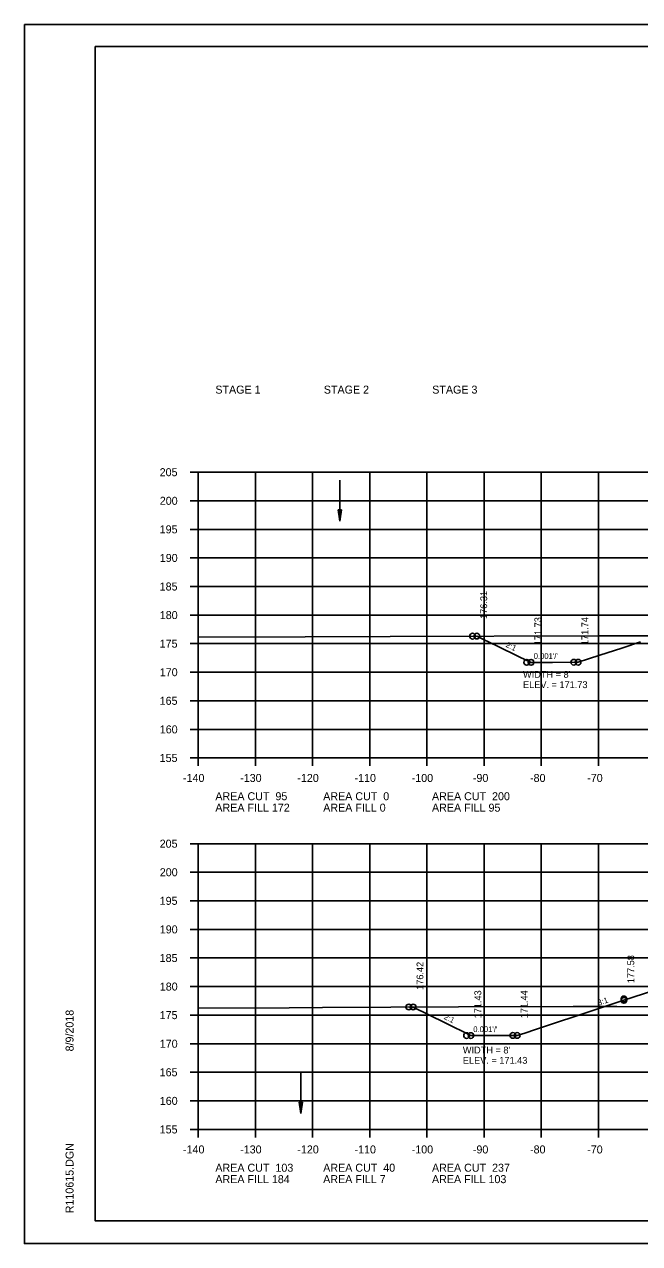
# Model space of a CAD drawing. Extents: x 1372132 to 1372465, y 380083 to 381790.
# Drawn here: x 1372131.6 to 1372239.2, y 381150.2 to 381363.5 of the extents above; entities that cross this region are included whole.
import ezdxf

# ---------------------------------------------------------------- set-up
doc = ezdxf.new("R2010")
doc.units = 0
for name, color, linetype in [('R_Axis', 7, 'Continuous'), ('R_Axis Annot', 7, 'Continuous'), ('R_Border', 7, 'Continuous'), ('R_Dimension', 7, 'Continuous'), ('R_Draft', 7, 'Continuous'), ('R_Exist Surface', 7, 'Continuous'), ('R_Fin Surface', 7, 'Continuous'), ('R_Grid', 7, 'Continuous'), ('R_No Plot', 7, 'Continuous'), ('R_Xsect Elev', 7, 'Continuous'), ('R_Xsect Slope', 7, 'Continuous')]:
    doc.layers.add(name, color=color, linetype=linetype)

msp = doc.modelspace()

# ---------------------------------------------------------------- linework, layer by layer
at = {"layer": 'R_Axis'}
for p, q in [((1372160.61, 381285.16), (1372162.01, 381285.16)), ((1372162.01, 381235.16), (1372162.01, 381285.16)), ((1372160.61, 381280.16), (1372162.01, 381280.16)), ((1372160.61, 381275.16), (1372162.01, 381275.16)), ((1372160.61, 381270.16), (1372162.01, 381270.16)), ((1372160.61, 381265.16), (1372162.01, 381265.16)), ((1372160.61, 381260.16), (1372162.01, 381260.16)), ((1372160.61, 381255.16), (1372162.01, 381255.16)), ((1372160.61, 381250.16), (1372162.01, 381250.16)), ((1372160.61, 381245.16), (1372162.01, 381245.16)), ((1372160.61, 381240.16), (1372162.01, 381240.16)), ((1372160.61, 381235.16), (1372162.01, 381235.16)), ((1372162.01, 381235.16), (1372442.01, 381235.16)), ((1372162.01, 381233.76), (1372162.01, 381235.16)), ((1372172.01, 381233.76), (1372172.01, 381235.16)), ((1372182.01, 381233.76), (1372182.01, 381235.16)), ((1372192.01, 381233.76), (1372192.01, 381235.16)), ((1372202.01, 381233.76), (1372202.01, 381235.16)), ((1372212.01, 381233.76), (1372212.01, 381235.16)), ((1372222.01, 381233.76), (1372222.01, 381235.16)), ((1372232.01, 381233.76), (1372232.01, 381235.16)), ((1372160.61, 381220.16), (1372162.01, 381220.16)), ((1372162.01, 381170.16), (1372162.01, 381220.16)), ((1372160.61, 381215.16), (1372162.01, 381215.16)), ((1372160.61, 381210.16), (1372162.01, 381210.16)), ((1372160.61, 381205.16), (1372162.01, 381205.16)), ((1372160.61, 381200.16), (1372162.01, 381200.16)), ((1372160.61, 381195.16), (1372162.01, 381195.16)), ((1372160.61, 381190.16), (1372162.01, 381190.16)), ((1372160.61, 381185.16), (1372162.01, 381185.16)), ((1372160.61, 381180.16), (1372162.01, 381180.16)), ((1372160.61, 381175.16), (1372162.01, 381175.16)), ((1372160.61, 381170.16), (1372162.01, 381170.16)), ((1372162.01, 381170.16), (1372442.01, 381170.16)), ((1372162.01, 381168.76), (1372162.01, 381170.16)), ((1372172.01, 381168.76), (1372172.01, 381170.16)), ((1372182.01, 381168.76), (1372182.01, 381170.16)), ((1372192.01, 381168.76), (1372192.01, 381170.16)), ((1372202.01, 381168.76), (1372202.01, 381170.16)), ((1372212.01, 381168.76), (1372212.01, 381170.16)), ((1372222.01, 381168.76), (1372222.01, 381170.16)), ((1372232.01, 381168.76), (1372232.01, 381170.16))]:
    msp.add_line(p, q, dxfattribs=at)
at = {"layer": 'R_Border'}
for p, q in [((1372144.01, 381359.62), (1372460.19, 381359.62)), ((1372144.01, 381154.16), (1372144.01, 381359.62)), ((1372144.01, 381154.16), (1372144.01, 381154.16)), ((1372460.19, 381154.16), (1372144.01, 381154.16))]:
    msp.add_line(p, q, dxfattribs=at)
at = {"layer": 'R_Dimension'}
for p, q in [((1372186.49, 381278.6), (1372186.79, 381276.6)), ((1372187.09, 381278.6), (1372186.49, 381278.6)), ((1372186.49, 381278.6), (1372186.79, 381276.6)), ((1372187.09, 381278.6), (1372186.49, 381278.6)), ((1372186.54, 381278.6), (1372186.79, 381276.93)), ((1372186.54, 381278.6), (1372186.79, 381276.93)), ((1372186.59, 381278.6), (1372186.79, 381277.28)), ((1372186.59, 381278.6), (1372186.79, 381277.28)), ((1372186.64, 381278.6), (1372186.79, 381277.61)), ((1372186.64, 381278.6), (1372186.79, 381277.61)), ((1372186.69, 381278.6), (1372186.79, 381277.95)), ((1372186.69, 381278.6), (1372186.79, 381277.95)), ((1372186.74, 381278.6), (1372186.79, 381278.28)), ((1372186.74, 381278.6), (1372186.79, 381278.28)), ((1372187.09, 381278.6), (1372186.79, 381276.6)), ((1372186.88, 381278.6), (1372186.79, 381277.95)), ((1372186.99, 381278.6), (1372186.79, 381277.28)), ((1372187.04, 381278.6), (1372186.79, 381276.93)), ((1372186.94, 381278.6), (1372186.79, 381277.61)), ((1372186.83, 381278.6), (1372186.79, 381278.28)), ((1372187.09, 381278.6), (1372186.79, 381276.6)), ((1372186.88, 381278.6), (1372186.79, 381277.95)), ((1372186.99, 381278.6), (1372186.79, 381277.28)), ((1372187.04, 381278.6), (1372186.79, 381276.93)), ((1372186.94, 381278.6), (1372186.79, 381277.61)), ((1372186.83, 381278.6), (1372186.79, 381278.28)), ((1372179.67, 381174.92), (1372179.97, 381172.92)), ((1372180.27, 381174.92), (1372179.67, 381174.92)), ((1372179.67, 381174.92), (1372179.97, 381172.92)), ((1372180.27, 381174.92), (1372179.67, 381174.92)), ((1372179.72, 381174.92), (1372179.97, 381173.26)), ((1372179.72, 381174.92), (1372179.97, 381173.26)), ((1372179.78, 381174.92), (1372179.97, 381173.6)), ((1372179.78, 381174.92), (1372179.97, 381173.6)), ((1372179.83, 381174.92), (1372179.97, 381173.93)), ((1372179.83, 381174.92), (1372179.97, 381173.93)), ((1372179.88, 381174.92), (1372179.97, 381174.27)), ((1372179.88, 381174.92), (1372179.97, 381174.27)), ((1372179.93, 381174.92), (1372179.97, 381174.61)), ((1372179.93, 381174.92), (1372179.97, 381174.61)), ((1372180.27, 381174.92), (1372179.97, 381172.92)), ((1372180.07, 381174.92), (1372179.97, 381174.27)), ((1372180.17, 381174.92), (1372179.97, 381173.6)), ((1372180.22, 381174.92), (1372179.97, 381173.26)), ((1372180.12, 381174.92), (1372179.97, 381173.93)), ((1372180.02, 381174.92), (1372179.97, 381174.61)), ((1372180.27, 381174.92), (1372179.97, 381172.92)), ((1372180.07, 381174.92), (1372179.97, 381174.27)), ((1372180.17, 381174.92), (1372179.97, 381173.6)), ((1372180.22, 381174.92), (1372179.97, 381173.26)), ((1372180.12, 381174.92), (1372179.97, 381173.93)), ((1372180.02, 381174.92), (1372179.97, 381174.61))]:
    msp.add_line(p, q, dxfattribs=at)
at = {"layer": 'R_Draft'}
for p, q in [((1372186.79, 381283.74), (1372186.79, 381276.6)), ((1372179.97, 381180.06), (1372179.97, 381172.92))]:
    msp.add_line(p, q, dxfattribs=at)
at = {"layer": 'R_Exist Surface'}
for points in [[(1372162.01, 381256.31), (1372180.72, 381256.37), (1372195.57, 381256.42), (1372231.92, 381256.55), (1372236.05, 381256.54), (1372246.27, 381256.51)], [(1372162.01, 381191.38), (1372177.94, 381191.45), (1372183.73, 381191.49), (1372195.68, 381191.57), (1372207.54, 381191.6), (1372227.58, 381191.66), (1372233.91, 381191.66), (1372235.26, 381191.67), (1372245.67, 381191.63)]]:
    msp.add_lwpolyline(points, dxfattribs=at)
at = {"layer": 'R_Fin Surface'}
for points in [[(1372210.75, 381256.48), (1372211.92, 381255.91), (1372214.24, 381254.78), (1372218.17, 381252.88), (1372220.22, 381251.89), (1372223.99, 381251.89), (1372228.45, 381251.9), (1372230.29, 381252.49), (1372232.23, 381253.12), (1372236.11, 381254.39), (1372239.36, 381255.46)], [(1372199.6, 381191.58), (1372205.21, 381188.81), (1372209.72, 381186.59), (1372212.24, 381186.6), (1372217.82, 381186.6), (1372219.13, 381187.03), (1372221.02, 381187.66), (1372231.75, 381191.19), (1372236.48, 381192.75), (1372241.71, 381194.47), (1372246.57, 381196.07), (1372247.93, 381196.05), (1372248.58, 381196.04), (1372251.05, 381196), (1372258.67, 381195.91), (1372258.96, 381195.91), (1372259.99, 381195.89), (1372268.77, 381195.71), (1372270.22, 381195.68), (1372270.79, 381195.67), (1372276.29, 381193.86), (1372279.11, 381192.93)]]:
    msp.add_lwpolyline(points, dxfattribs=at)
at = {"layer": 'R_Grid'}
for p, q in [((1372162.01, 381285.16), (1372442.01, 381285.16)), ((1372162.01, 381235.16), (1372162.01, 381285.16)), ((1372172.01, 381235.16), (1372172.01, 381285.16)), ((1372182.01, 381235.16), (1372182.01, 381285.16)), ((1372192.01, 381235.16), (1372192.01, 381285.16)), ((1372202.01, 381235.16), (1372202.01, 381285.16)), ((1372212.01, 381235.16), (1372212.01, 381285.16)), ((1372222.01, 381235.16), (1372222.01, 381285.16)), ((1372232.01, 381235.16), (1372232.01, 381285.16)), ((1372162.01, 381280.16), (1372442.01, 381280.16)), ((1372162.01, 381275.16), (1372442.01, 381275.16)), ((1372162.01, 381270.16), (1372442.01, 381270.16)), ((1372162.01, 381265.16), (1372442.01, 381265.16)), ((1372162.01, 381260.16), (1372442.01, 381260.16)), ((1372162.01, 381255.16), (1372442.01, 381255.16)), ((1372162.01, 381250.16), (1372442.01, 381250.16)), ((1372162.01, 381245.16), (1372442.01, 381245.16)), ((1372162.01, 381240.16), (1372442.01, 381240.16)), ((1372162.01, 381235.16), (1372442.01, 381235.16)), ((1372162.01, 381220.16), (1372442.01, 381220.16)), ((1372162.01, 381170.16), (1372162.01, 381220.16)), ((1372172.01, 381170.16), (1372172.01, 381220.16)), ((1372182.01, 381170.16), (1372182.01, 381220.16)), ((1372192.01, 381170.16), (1372192.01, 381220.16)), ((1372202.01, 381170.16), (1372202.01, 381220.16)), ((1372212.01, 381170.16), (1372212.01, 381220.16)), ((1372222.01, 381170.16), (1372222.01, 381220.16)), ((1372232.01, 381170.16), (1372232.01, 381220.16)), ((1372162.01, 381215.16), (1372442.01, 381215.16)), ((1372162.01, 381210.16), (1372442.01, 381210.16)), ((1372162.01, 381205.16), (1372442.01, 381205.16)), ((1372162.01, 381200.16), (1372442.01, 381200.16)), ((1372162.01, 381195.16), (1372442.01, 381195.16)), ((1372162.01, 381190.16), (1372442.01, 381190.16)), ((1372162.01, 381185.16), (1372442.01, 381185.16)), ((1372162.01, 381180.16), (1372442.01, 381180.16)), ((1372162.01, 381175.16), (1372442.01, 381175.16)), ((1372162.01, 381170.16), (1372442.01, 381170.16))]:
    msp.add_line(p, q, dxfattribs=at)
at = {"layer": 'R_No Plot'}
for p, q in [((1372131.61, 381363.52), (1372464.95, 381363.52)), ((1372131.61, 381150.18), (1372464.95, 381150.18))]:
    msp.add_line(p, q, dxfattribs=at)
for points in [[(1372131.61, 381363.52), (1372464.95, 381363.52), (1372464.95, 381150.18), (1372131.61, 381150.18)], [(1372377.93, 381359.62), (1372377.93, 381349.74), (1372413.67, 381349.74), (1372413.67, 381346.82), (1372436.87, 381346.82), (1372436.87, 381322.49), (1372460.19, 381322.49), (1372460.19, 381154.16), (1372144.01, 381154.16), (1372144.01, 381359.62)]]:
    msp.add_lwpolyline(points, close=True, dxfattribs=at)
for centre in [(1372210, 381256.47), (1372210.75, 381256.48), (1372219.47, 381251.89), (1372220.22, 381251.89), (1372227.7, 381251.9), (1372228.45, 381251.9), (1372198.85, 381191.58), (1372199.6, 381191.58), (1372236.48, 381192.99), (1372236.48, 381192.75), (1372208.96, 381186.59), (1372209.72, 381186.59), (1372217.06, 381186.6), (1372217.82, 381186.6)]:
    msp.add_circle(centre, 0.5, dxfattribs=at)

# ---------------------------------------------------------------- texts
at = {"layer": 'R_Axis Annot'}
for s, p in [('STAGE 1', (1372165.01, 381298.91)), ('STAGE 2', (1372183.98, 381298.91)), ('STAGE 3', (1372202.94, 381298.91)), ('205', (1372155.27, 381284.46)), ('200', (1372155.29, 381279.46)), ('195', (1372155.27, 381274.46)), ('190', (1372155.29, 381269.46)), ('185', (1372155.27, 381264.46)), ('180', (1372155.29, 381259.46)), ('175', (1372155.27, 381254.46)), ('170', (1372155.29, 381249.46)), ('165', (1372155.27, 381244.46)), ('160', (1372155.29, 381239.46)), ('155', (1372155.27, 381234.46)), ('-140', (1372159.35, 381230.96)), ('-130', (1372169.35, 381230.96)), ('-120', (1372179.35, 381230.96)), ('-110', (1372189.35, 381230.96)), ('-100', (1372199.35, 381230.96)), ('-90', (1372210.05, 381230.96)), ('-80', (1372220.05, 381230.96)), ('-70', (1372230.05, 381230.96)), ('AREA CUT  95', (1372165.01, 381227.76)), ('AREA CUT  0', (1372183.87, 381227.76)), ('AREA CUT  200', (1372202.9, 381227.76)), ('AREA FILL 172', (1372165.01, 381225.76)), ('AREA FILL 0', (1372183.87, 381225.76)), ('AREA FILL 95', (1372202.9, 381225.76)), ('205', (1372155.27, 381219.46)), ('200', (1372155.29, 381214.46)), ('195', (1372155.27, 381209.46)), ('190', (1372155.29, 381204.46)), ('185', (1372155.27, 381199.46)), ('180', (1372155.29, 381194.46)), ('175', (1372155.27, 381189.46)), ('170', (1372155.29, 381184.46)), ('165', (1372155.27, 381179.46)), ('160', (1372155.29, 381174.46)), ('155', (1372155.27, 381169.46)), ('-140', (1372159.35, 381165.96)), ('-130', (1372169.35, 381165.96)), ('-120', (1372179.35, 381165.96)), ('-110', (1372189.35, 381165.96)), ('-100', (1372199.35, 381165.96)), ('-90', (1372210.05, 381165.96)), ('-80', (1372220.05, 381165.96)), ('-70', (1372230.05, 381165.96)), ('AREA CUT  103', (1372165.01, 381162.76)), ('AREA CUT  40', (1372183.87, 381162.76)), ('AREA CUT  237', (1372202.9, 381162.76)), ('AREA FILL 184', (1372165.01, 381160.76)), ('AREA FILL 7', (1372183.87, 381160.76)), ('AREA FILL 103', (1372202.9, 381160.76))]:
    msp.add_text(s, height=1.4, dxfattribs=at).set_placement(p)
at = {"layer": 'R_Border'}
for s, p in [('8/9/2018', (1372140.21, 381183.81)), ('R110615.DGN', (1372140.21, 381155.49))]:
    msp.add_text(s, height=1.4, rotation=90, dxfattribs=at).set_placement(p)
at = {"layer": 'R_Dimension'}
for s, p in [("WIDTH = 8'", (1372218.82, 381249.18)), ('ELEV. = 171.73', (1372218.82, 381247.38)), ("WIDTH = 8'", (1372208.3, 381183.45)), ('ELEV. = 171.43', (1372208.3, 381181.65))]:
    msp.add_text(s, height=1.2, dxfattribs=at).set_placement(p)
at = {"layer": 'R_Xsect Elev'}
for s, p in [('176.31', (1372212.55, 381259.48)), ('171.73', (1372222.02, 381254.89)), ('171.74', (1372230.25, 381254.9)), ('177.58', (1372238.28, 381195.75)), ('176.42', (1372201.4, 381194.58)), ('171.43', (1372211.52, 381189.59)), ('171.44', (1372219.62, 381189.6))]:
    msp.add_text(s, height=1.2, rotation=90, dxfattribs=at).set_placement(p)
at = {"layer": 'R_Xsect Slope'}
for s, rotation, p in [('2:1', 334.1523, (1372215.7, 381254.63)), ("0.001'/'", 0.0708, (1372220.69, 381252.49)), ('3:1', 18.2313, (1372232.04, 381191.81)), ('2:1', 333.7615, (1372204.88, 381189.53)), ("0.001'/'", 0.0417, (1372210.12, 381187.19))]:
    msp.add_text(s, height=1, rotation=rotation, dxfattribs=at).set_placement(p)

doc.saveas('drawing.dxf')
